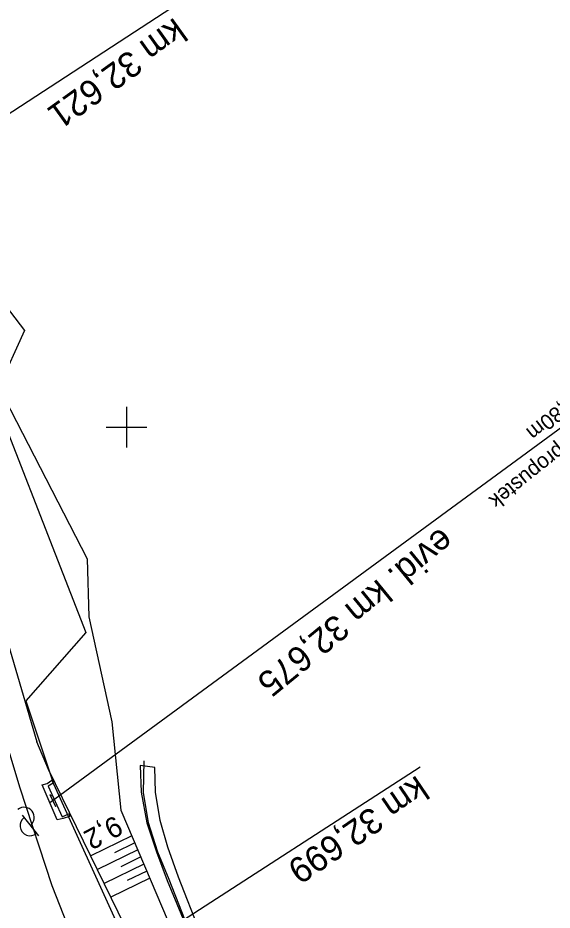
# Model space of a CAD drawing. Extents: x -804166 to -803706, y -1151030 to -1150147.
# Drawn here: x -803910.7 to -803858.2, y -1150447.5 to -1150359.8 of the extents above; entities that cross this region are included whole.
import ezdxf

# ---------------------------------------------------------------- set-up
doc = ezdxf.new("R2010")
doc.units = 0
for name, color, linetype in [('0381KM032-037P - Vrstva 1', 7, 'Continuous'), ('0381KM032-037P - Vrstva 13', 7, 'Continuous'), ('0381KM032-037P - Vrstva 17', 7, 'Continuous'), ('0381KM032-037P - Vrstva 19', 7, 'Continuous'), ('0381KM032-037P - Vrstva 25', 7, 'Continuous'), ('0381KM032-037P - Vrstva 3', 7, 'Continuous'), ('0381KM032-037P - Vrstva 48', 7, 'Continuous'), ('0381KM032-037P - Vrstva 49', 7, 'Continuous'), ('hran DP - hran DP', 7, 'Continuous'), ('krizky_1000 - Vrstva 1', 7, 'Continuous')]:
    doc.layers.add(name, color=color, linetype=linetype)

msp = doc.modelspace()

# ---------------------------------------------------------------- linework, layer by layer
at = {"layer": '0381KM032-037P - Vrstva 1'}
msp.add_lwpolyline([(-804011.14, -1150262.39), (-804005.45, -1150273.41), (-803998.73, -1150284.85), (-803991.51, -1150295.63), (-803978.8, -1150312.77), (-803963.69, -1150332.99), (-803952.21, -1150348.36), (-803946.3, -1150356.39), (-803941.6, -1150363.14), (-803936.71, -1150370.83), (-803932.05, -1150378.84), (-803927.78, -1150386.91), (-803924.06, -1150395.18), (-803920.62, -1150403.65), (-803918.06, -1150410.86), (-803915.07, -1150420.32), (-803912.96, -1150427.25), (-803910.49, -1150435.34), (-803907.334, -1150445.05), (-803903.668, -1150454.381), (-803897.938, -1150464.596), (-803891.973, -1150476.598)], dxfattribs=at)
at = {"layer": '0381KM032-037P - Vrstva 13'}
msp.add_lwpolyline([(-803875.883, -1150484.91), (-803874.859, -1150484.495), (-803883.662, -1150468.351), (-803886.496, -1150463.09), (-803890.342, -1150455.103), (-803892.739, -1150449.637), (-803894.892, -1150444.207), (-803895.921, -1150441.276), (-803896.676, -1150438.635), (-803897.147, -1150435.872), (-803897.2, -1150433.432), (-803898.654, -1150433.258), (-803898.54, -1150435.86), (-803897.995, -1150438.863), (-803897.041, -1150441.738), (-803895.987, -1150444.528), (-803893.704, -1150450.064), (-803891.289, -1150455.545), (-803887.412, -1150463.602)], close=True, dxfattribs=at)
at = {"layer": '0381KM032-037P - Vrstva 17'}
msp.add_lwpolyline([(-803875.87, -1150484.459), (-803884.486, -1150468.8), (-803887.25, -1150463.566), (-803891.192, -1150455.528), (-803893.615, -1150450.032), (-803895.787, -1150444.436), (-803896.9, -1150441.761), (-803897.818, -1150438.885), (-803898.314, -1150435.883), (-803898.256, -1150432.783)], dxfattribs=at)
at = {"layer": '0381KM032-037P - Vrstva 19'}
for p, q in [((-803907.537, -1150436.866), (-803852.112, -1150396.222)), ((-803907.526, -1150436.102), (-803907.373, -1150436.242))]:
    msp.add_line(p, q, dxfattribs=at)
for points in [[(-803908.281, -1150435.147), (-803907.8, -1150435.023), (-803907.337, -1150434.681), (-803907.197, -1150434.991), (-803907.689, -1150435.265), (-803906.318, -1150438.295), (-803905.582, -1150437.956), (-803905.605, -1150438.249), (-803906.227, -1150438.463), (-803906.793, -1150438.584), (-803908.281, -1150435.147)], [(-803907.526, -1150436.102), (-803906.954, -1150437.281), (-803906.898, -1150437.161)]]:
    msp.add_lwpolyline(points, dxfattribs=at)
at = {"layer": '0381KM032-037P - Vrstva 25'}
msp.add_line((-803910.235, -1150438.115), (-803908.637, -1150440.166), dxfattribs=at)
for centre, start, end in [((-803910.051, -1150438.352), 307.9199, 127.9199), ((-803909.446, -1150439.148), 127.21733, 308.62248)]:
    msp.add_arc(centre, 1, start, end, dxfattribs=at)
at = {"layer": '0381KM032-037P - Vrstva 3'}
for p, q in [((-803948.983, -1150393.601), (-803893.865, -1150357.656)), ((-803903.668, -1150454.381), (-803871.126, -1150433.376))]:
    msp.add_line(p, q, dxfattribs=at)
at = {"layer": '0381KM032-037P - Vrstva 48'}
for p, q in [((-803899.465, -1150440.159), (-803903.499, -1150442.127)), ((-803899.171, -1150440.85), (-803901.17, -1150441.826)), ((-803898.877, -1150441.541), (-803902.841, -1150443.475)), ((-803898.583, -1150442.232), (-803900.547, -1150443.191)), ((-803898.289, -1150442.923), (-803902.183, -1150444.823)), ((-803897.995, -1150443.614), (-803899.924, -1150444.556)), ((-803897.7, -1150444.305), (-803901.525, -1150446.172))]:
    msp.add_line(p, q, dxfattribs=at)
at = {"layer": '0381KM032-037P - Vrstva 49'}
for points in [[(-804010.873, -1150255.863), (-804001.608, -1150274.672), (-803994.699, -1150286.679), (-803981.461, -1150304.357), (-803936.046, -1150366.093), (-803921.768, -1150392.538), (-803912.222, -1150419.282), (-803908.812, -1150430.908)], [(-803920.94, -1150376.21), (-803910.018, -1150390.511), (-803912.553, -1150396.059), (-803903.866, -1150412.95), (-803903.684, -1150418.644), (-803901.421, -1150428.97), (-803900.537, -1150437.639), (-803895.89, -1150448.56), (-803892.01, -1150457.3), (-803887.412, -1150463.602), (-803875.883, -1150484.91), (-803874.859, -1150484.495), (-803872.322, -1150492.497), (-803872.997, -1150496.546), (-803874.041, -1150498.946)], [(-803877.416, -1150484.532), (-803894.615, -1150460.334), (-803907.648, -1150433.624), (-803908.812, -1150430.908)]]:
    msp.add_lwpolyline(points, dxfattribs=at)
at = {"layer": 'hran DP - hran DP'}
for p, q in [((-803912.08, -1150399.4), (-803907, -1150412.45)), ((-803907, -1150412.45), (-803903.99, -1150420.19)), ((-803903.99, -1150420.19), (-803909.89, -1150426.9)), ((-803909.89, -1150426.9), (-803907.15, -1150435.03)), ((-803907.15, -1150435.03), (-803900.76, -1150449.16))]:
    msp.add_line(p, q, dxfattribs=at)
at = {"layer": 'krizky_1000 - Vrstva 1'}
for points in [[(-803900, -1150398), (-803900, -1150402)], [(-803902, -1150400), (-803898, -1150400)]]:
    msp.add_lwpolyline(points, dxfattribs=at)

# ---------------------------------------------------------------- texts
at = {"layer": '0381KM032-037P - Vrstva 19'}
for s, height, rotation, p in [('sv.0,80m', 1.5, 218.40951, (-803854.481, -1150395.216)), ('Trubní propustek', 1.5, 218.40951, (-803852.617, -1150397.567)), ('evid. km 32,675', 2.5, 219.34557, (-803869.096, -1150409.764))]:
    msp.add_text(s, height=height, rotation=rotation, dxfattribs=at).set_placement(p)
at = {"layer": '0381KM032-037P - Vrstva 3'}
for s, rotation, p in [('km 32,621', 215.71645, (-803895.272, -1150359.687)), ('km 32,699', 214.2898, (-803871.457, -1150434.149))]:
    msp.add_text(s, height=2.5, rotation=rotation, dxfattribs=at).set_placement(p)
at = {"layer": '0381KM032-037P - Vrstva 48'}
msp.add_text('9,2', height=2, rotation=208.05026, dxfattribs=at).set_placement((-803901.085, -1150438.096))

doc.saveas('drawing.dxf')
